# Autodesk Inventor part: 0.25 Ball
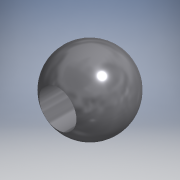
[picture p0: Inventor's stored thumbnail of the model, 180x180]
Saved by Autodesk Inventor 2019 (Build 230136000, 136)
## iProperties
Shininess: 60.0
Length Units: 11272
Angle Units: 11279
Time Units: 11290
Mass Units: 11286
Length Display Precision: 4
Angle Display Precision: 2
Compacted: True
Company: Autodesk
Created: 2000-03
Part Number: 0.25 Ball
Project: Inventor Samples
User Status: IN PROGRESS
Material: Aluminum
Document SubType Name: Modeling
Designer: Autodesk, Inc.
Density: 2.71 g/cm^3
Mass: 0.235983 g
Surface Area: 1.64558 cm^2
Volume: 0.0870787 cm^3
Appearance: Metal-Steel
Density: 0.0
Volumn: 0.0
Area: 0.0
PropertySet Name: Model Information
Control State: 0
Master: False
Checked Out: False
Checked Out Date: 2018-05-30
Last Check In Date: 2018-05-30
Author: Autodesk, Inc.
Revision Number: A
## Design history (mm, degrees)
sketch "Sketch2"
  geometry: L1 (-7.772, 2.624)-(-7.772, -3.726); C1 r 1.587 at (-7.772, -0.551); A1 r 3.175 centre (-7.772, -0.551) between (-7.772, 2.624) and (-7.772, -3.726)
  constraints: 2 centre point, 2 end point, 2 point on circle, 1 coincident, 1 midpoint, 1 vertical
  dimensions: "d0" = 6.35 diameter of A1; "d1" = 3.175 diameter of C1
node "Revolution1" dims "d2" = 90 deg
node "Extrusion1" dims "d3" = 25.4, "d4" = 0
workaxis "Work Axis1"
workplane "Work Plane1"
body "Solid1"
other parameters: "d7" = 90 deg, "d9" = 0.889
